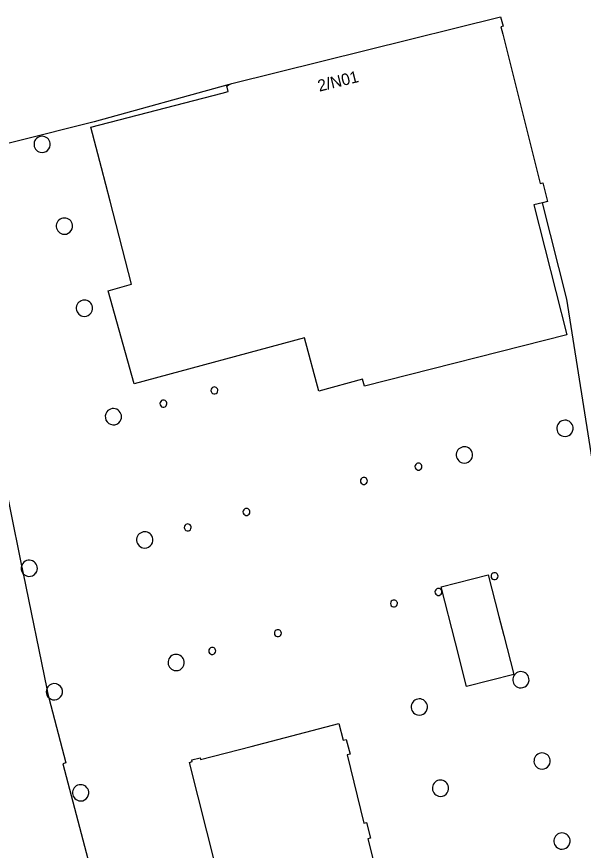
# Model space of a CAD drawing. Extents: x 160806 to 161707, y 383697 to 384148.
# Drawn here: x 161282.3 to 161331, y 383993.1 to 384064.8 of the extents above; entities that cross this region are included whole.
import ezdxf

# ---------------------------------------------------------------- set-up
doc = ezdxf.new("R2010")
doc.units = 0
for name, color, linetype in [('IMGEO_Pand', 7, 'Continuous'), ('IMGEO_Pand_nummerreeks', 7, 'Continuous'), ('IMGEO_Pand_overbouw', 7, 'Continuous')]:
    doc.layers.add(name, color=color, linetype=linetype)

msp = doc.modelspace()

# ---------------------------------------------------------------- linework, layer by layer
at = {"layer": 'IMGEO_Pand'}
for points in [[(161329.552, 384037.396), (161312.15, 384032.996), (161312.003, 384033.577), (161308.24, 384032.557), (161306.994, 384037.151), (161292.363, 384033.183), (161290.108, 384041.184), (161292.135, 384041.772), (161290.281, 384048.897), (161289.537, 384051.757), (161288.622, 384055.273), (161299.916, 384058.201), (161300.442, 384058.338), (161300.327, 384058.807), (161300.359, 384058.83), (161300.535, 384058.932), (161300.766, 384059.009), (161323.868, 384064.767), (161324.075, 384063.942), (161323.889, 384063.895), (161324.046, 384063.267), (161327.253, 384050.405), (161327.487, 384050.462), (161327.896, 384048.869), (161327.455, 384048.758), (161326.709, 384048.571), (161329.552, 384037.396)], [(161322.794, 384016.755), (161323.71, 384013.167), (161324.13, 384011.53), (161324.988, 384008.199), (161320.919, 384007.16), (161319.972, 384010.899), (161318.753, 384015.717), (161322.794, 384016.755)], [(161310.919, 384001.335), (161310.658, 384001.268), (161312.108, 383995.404), (161312.338, 383995.464), (161312.682, 383994.096), (161312.451, 383994.037), (161313.62, 383989.378), (161313.677, 383989.154), (161313.593, 383989.134), (161313.129, 383989.019), (161300.843, 383985.84), (161297.111, 384000.629), (161297.354, 384000.692), (161297.319, 384000.838), (161298.032, 384001.03), (161298.073, 384000.878), (161302.412, 384002.002), (161309.96, 384003.959), (161310.329, 384002.536), (161310.591, 384002.604), (161310.919, 384001.335)]]:
    msp.add_lwpolyline(points, dxfattribs=at)
for centre, radius, start, end in [((161284.444, 384053.784), 0.7, 7.86697, 256.86736), ((161284.444, 384053.785), 0.701, 256.92932, 7.805), ((161286.357, 384046.75), 0.7, 7.89294, 256.84138), ((161286.358, 384046.75), 0.7, 256.81442, 7.91991), ((161288.076, 384039.689), 0.7, 7.86697, 256.86736), ((161288.076, 384039.69), 0.701, 256.92932, 7.805), ((161299.255, 384032.616), 0.3, 119.96327, 360), ((161299.255, 384032.616), 0.3, 359.96327, 119.99999), ((161294.87, 384031.48), 0.3, 119.96327, 0), ((161294.87, 384031.48), 0.3, 359.96327, 119.99999), ((161290.571, 384030.36), 0.7, 143.3683, 326.051), ((161290.57, 384030.359), 0.7, 326.13202, 143.28729), ((161329.397, 384029.359), 0.7, 7.89294, 256.84138), ((161329.398, 384029.359), 0.7, 256.81442, 7.91991), ((161320.751, 384027.07), 0.7, 7.90192, 256.8324), ((161320.752, 384027.07), 0.7, 256.81442, 7.91991), ((161316.8, 384026.069), 0.3, 119.96327, 0), ((161316.8, 384026.069), 0.3, 359.96327, 119.99999), ((161312.11, 384024.832), 0.3, 120.05881, 359.90445), ((161312.11, 384024.831), 0.3, 359.96327, 119.99999), ((161302.012, 384022.167), 0.3, 119.96327, 0), ((161302.012, 384022.167), 0.3, 359.96327, 119.99999), ((161296.962, 384020.834), 0.3, 120.05881, 0.09555), ((161296.962, 384020.834), 0.3, 0.15448, 119.99988), ((161293.268, 384019.76), 0.7, 7.90192, 256.8324), ((161293.269, 384019.76), 0.7, 256.81442, 7.91991), ((161283.338, 384017.319), 0.7, 324.72561, 143.4001), ((161283.338, 384017.319), 0.7, 143.34063, 324.78508), ((161323.346, 384016.638), 0.3, 120.05881, 359.90445), ((161323.346, 384016.637), 0.3, 359.96327, 119.99999), ((161318.518, 384015.284), 0.3, 119.96327, 0), ((161318.518, 384015.284), 0.3, 359.96327, 119.99999), ((161314.695, 384014.29), 0.3, 119.96327, 360), ((161314.695, 384014.29), 0.3, 359.96327, 119.99999), ((161304.717, 384011.737), 0.3, 119.96327, 0), ((161304.717, 384011.737), 0.3, 359.96327, 119.99999), ((161295.966, 384009.215), 0.7, 7.90192, 256.8324), ((161299.072, 384010.212), 0.3, 120.05881, 0.09555), ((161299.072, 384010.211), 0.3, 0.15448, 119.99988), ((161295.967, 384009.215), 0.7, 256.81442, 7.91991), ((161325.608, 384007.732), 0.7, 7.86697, 256.86736), ((161325.608, 384007.733), 0.701, 256.92932, 7.805), ((161285.494, 384006.699), 0.701, 143.41211, 242.01965), ((161285.493, 384006.7), 0.7, 7.82629, 143.41531), ((161285.493, 384006.699), 0.7, 242.05301, 7.90092), ((161316.873, 384005.389), 0.7, 7.86697, 256.86736), ((161316.873, 384005.39), 0.701, 256.92932, 7.805), ((161327.431, 384000.739), 0.7, 7.86697, 256.86736), ((161327.431, 384000.74), 0.701, 256.92932, 7.805), ((161287.757, 383998.008), 0.7, 7.92796, 256.80637), ((161318.696, 383998.405), 0.7, 7.86697, 256.86736), ((161318.696, 383998.406), 0.701, 256.92932, 7.805), ((161287.757, 383998.009), 0.7, 256.81442, 7.91991), ((161329.141, 383993.857), 0.7, 7.89294, 256.84138), ((161329.142, 383993.857), 0.7, 256.81442, 7.91991)]:
    msp.add_arc(centre, radius, start, end, dxfattribs=at)
at = {"layer": 'IMGEO_Pand_overbouw'}
for points in [[(161334.948, 384006.439), (161329.556, 384040.465), (161327.455, 384048.758), (161326.709, 384048.571), (161329.552, 384037.396), (161312.15, 384032.996), (161312.003, 384033.577), (161308.24, 384032.557), (161306.994, 384037.151), (161292.363, 384033.183), (161290.108, 384041.184), (161292.135, 384041.772), (161290.281, 384048.897), (161289.537, 384051.757), (161288.622, 384055.273), (161299.916, 384058.201), (161300.442, 384058.338), (161300.327, 384058.807), (161300.359, 384058.83), (161300.535, 384058.932), (161288.93, 384055.736), (161275.531, 384052.366)], [(161280.625, 384027.497), (161282.668, 384017.523), (161282.801, 384016.859), (161284.836, 384006.941), (161284.897, 384006.643), (161285.017, 384006.185), (161286.486, 384000.594), (161286.226, 384000.503), (161290.822, 383983.081)]]:
    msp.add_lwpolyline(points, dxfattribs=at)

# ---------------------------------------------------------------- texts
at = {"layer": 'IMGEO_Pand_nummerreeks'}
msp.add_text('2/N01', height=1, rotation=13.79682, dxfattribs=at).set_placement((161308.273, 384058.312))

doc.saveas('drawing.dxf')
